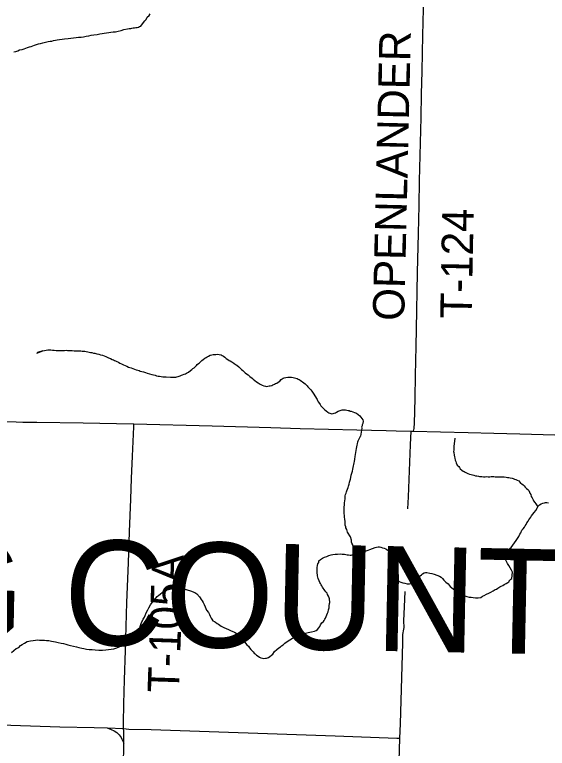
# Model space of a CAD drawing. Extents: x 2.1 to 73.9, y 4 to 26.
# Drawn here: x 42.758 to 43.238, y 21.599 to 22.261 of the extents above; entities that cross this region are included whole.
import ezdxf

# ---------------------------------------------------------------- set-up
doc = ezdxf.new("R2010")
doc.units = 0
for name, color, linetype in [('GM_X_County_Road', 7, 'Continuous'), ('GM_X_County_Text', 7, 'Continuous'), ('GM_X_Minor_River', 7, 'Continuous'), ('GM_X_Township_Road', 7, 'Continuous'), ('GM_X_Township_Road_Text', 7, 'Continuous')]:
    doc.layers.add(name, color=color, linetype=linetype)

msp = doc.modelspace()

# ---------------------------------------------------------------- linework, layer by layer
at = {"layer": 'GM_X_County_Road'}
msp.add_line((42.841, 21.61699), (42.85577, 21.61649), dxfattribs=at)
for points in [[(42.60148, 21.62491), (42.61023, 21.62468), (42.63041, 21.62408), (42.65683, 21.62308), (42.68634, 21.62181), (42.70341, 21.62107), (42.71739, 21.62063), (42.73602, 21.62004), (42.79819, 21.61818), (42.82928, 21.61742), (42.841, 21.61699)], [(42.841, 21.61699), (42.84468, 21.61557), (42.84745, 21.61451), (42.8499, 21.61286), (42.85199, 21.61075), (42.85365, 21.6083), (42.85431, 21.60697), (42.8562, 21.60316)], [(42.8562, 21.60316), (42.85611, 21.61101), (42.85596, 21.61379), (42.85577, 21.61649)], [(42.85049, 21.4548), (42.85056, 21.46392), (42.85093, 21.47093), (42.85226, 21.50191), (42.85575, 21.58424), (42.85622, 21.60133), (42.8562, 21.60316)]]:
    msp.add_lwpolyline(points, dxfattribs=at)
at = {"layer": 'GM_X_Minor_River'}
for points in [[(42.86803, 22.24923), (42.86937, 22.24959), (42.87032, 22.24996), (42.87128, 22.25032), (42.87206, 22.25126), (42.87516, 22.2552), (42.87613, 22.25632), (42.87711, 22.2584), (42.87885, 22.25989), (42.87982, 22.2614)], [(42.75662, 22.22706), (42.75853, 22.2276), (42.76025, 22.22814), (42.76197, 22.22887), (42.76426, 22.22941), (42.76598, 22.22995), (42.7677, 22.23049), (42.76923, 22.23104), (42.77076, 22.23158), (42.77229, 22.23213), (42.77401, 22.23267), (42.77554, 22.23322), (42.77726, 22.23376), (42.77898, 22.2343), (42.7807, 22.23466), (42.78299, 22.23519), (42.78776, 22.23644), (42.78948, 22.2368), (42.791, 22.23696), (42.79272, 22.23731), (42.79425, 22.23767), (42.79597, 22.23802), (42.79806, 22.23818), (42.80035, 22.23852), (42.80264, 22.23887), (42.80587, 22.2392), (42.80835, 22.23954), (42.81064, 22.23969), (42.81292, 22.24003), (42.81521, 22.24038), (42.81749, 22.24053), (42.81959, 22.24088), (42.82207, 22.24122), (42.82436, 22.24175), (42.82665, 22.2421), (42.82894, 22.24244), (42.83199, 22.24296), (42.83428, 22.2435), (42.83638, 22.24384), (42.83847, 22.244), (42.84038, 22.24435), (42.84247, 22.24451), (42.84438, 22.24486), (42.84648, 22.2452), (42.84857, 22.24536), (42.85105, 22.24589), (42.85372, 22.24642), (42.85621, 22.24733), (42.85926, 22.24785), (42.86098, 22.2482), (42.86231, 22.24837), (42.86326, 22.24855), (42.86441, 22.24872), (42.86574, 22.24889), (42.86689, 22.24906), (42.86803, 22.24923)], [(42.77766, 21.95539), (42.78282, 21.95721), (42.77804, 21.95596), (42.78282, 21.95721), (42.78454, 21.95757), (42.78606, 21.95792), (42.7874, 21.95828), (42.78892, 21.95826), (42.79025, 21.95823), (42.79177, 21.95802), (42.79329, 21.958), (42.795, 21.95778), (42.79728, 21.95755), (42.79918, 21.95752), (42.80089, 21.95769), (42.80241, 21.95766), (42.80394, 21.95783), (42.80527, 21.95781), (42.8066, 21.95779), (42.80812, 21.95776), (42.80945, 21.95774), (42.81135, 21.95733), (42.81325, 21.9573), (42.81534, 21.95727), (42.81724, 21.95724), (42.81857, 21.95703), (42.81971, 21.95701), (42.82085, 21.95699), (42.82464, 21.95617), (42.82597, 21.95596), (42.82711, 21.95575), (42.82862, 21.95535), (42.82995, 21.95514), (42.83185, 21.95473), (42.83355, 21.95432), (42.83506, 21.95372), (42.83677, 21.95332), (42.83847, 21.95272), (42.83979, 21.95213), (42.84112, 21.95154), (42.84225, 21.95114), (42.8432, 21.95075), (42.84414, 21.95035), (42.84565, 21.94957), (42.84678, 21.94917), (42.84773, 21.94858), (42.84867, 21.94819), (42.8498, 21.9476), (42.85112, 21.94701), (42.85244, 21.94623), (42.85396, 21.94564), (42.85566, 21.94485), (42.85716, 21.94406), (42.85887, 21.94347), (42.86038, 21.94268), (42.86265, 21.94189), (42.86416, 21.94129), (42.86567, 21.9407), (42.86718, 21.94011), (42.8687, 21.93989), (42.86983, 21.93949), (42.87097, 21.9391), (42.87229, 21.93869), (42.87381, 21.93829), (42.87551, 21.93769), (42.87722, 21.93729), (42.87911, 21.9365), (42.88138, 21.93608), (42.8829, 21.93568), (42.88441, 21.93527), (42.88555, 21.93487), (42.88706, 21.93447), (42.88839, 21.93445), (42.88991, 21.93423), (42.89124, 21.93402), (42.89276, 21.93381), (42.89428, 21.93379), (42.89827, 21.93353), (42.89941, 21.93351), (42.90074, 21.93349), (42.90189, 21.93367), (42.90303, 21.93365), (42.90398, 21.93382), (42.90513, 21.93418), (42.90608, 21.93436), (42.90704, 21.93472), (42.908, 21.93528), (42.90915, 21.93583), (42.91049, 21.93638), (42.91163, 21.93674), (42.91259, 21.9373), (42.91451, 21.93821), (42.91624, 21.93971), (42.9174, 21.94045), (42.91836, 21.94138), (42.91951, 21.94213), (42.92164, 21.94399), (42.92241, 21.94493), (42.92338, 21.94587), (42.92434, 21.94661), (42.9253, 21.94736)], [(42.9253, 21.94736), (42.92665, 21.94866), (42.92762, 21.94941), (42.92935, 21.95071), (42.93031, 21.95127), (42.93127, 21.95201), (42.93242, 21.95256), (42.93415, 21.95348), (42.93548, 21.95384), (42.93663, 21.95402), (42.93796, 21.95418), (42.9391, 21.95417), (42.94024, 21.95434), (42.94385, 21.95371), (42.94498, 21.95312), (42.94611, 21.95253), (42.94724, 21.95176), (42.94836, 21.95041), (42.95006, 21.94943), (42.95119, 21.94865), (42.95213, 21.94826), (42.95364, 21.94748), (42.95533, 21.94631), (42.95703, 21.94514), (42.95797, 21.94456), (42.95984, 21.94282), (42.96153, 21.94127), (42.96247, 21.9405), (42.9636, 21.93953), (42.96453, 21.93856), (42.96566, 21.93759), (42.96697, 21.93662), (42.96848, 21.93565), (42.96998, 21.9343), (42.97186, 21.93275), (42.97298, 21.93178), (42.9743, 21.93062), (42.9758, 21.92945), (42.97731, 21.92848), (42.97825, 21.92789), (42.97919, 21.92731), (42.98089, 21.92633), (42.9824, 21.92574), (42.98391, 21.92533), (42.98486, 21.92532), (42.98734, 21.92566), (42.9883, 21.92583), (42.98963, 21.92619), (42.99059, 21.92656), (42.99212, 21.92729), (42.99308, 21.92785), (42.99423, 21.92821), (42.99557, 21.92914), (42.99692, 21.93007), (42.99827, 21.93138), (43, 21.93268), (43.00096, 21.93305), (43.0023, 21.9334), (43.0042, 21.93356), (43.00515, 21.93355), (43.00629, 21.93353), (43.00743, 21.93351), (43.00895, 21.9333), (43.01028, 21.93309), (43.01141, 21.93269), (43.01255, 21.93248), (43.01349, 21.9319), (43.01444, 21.9315), (43.01538, 21.93092), (43.01651, 21.92995), (43.01745, 21.92936), (43.01857, 21.92839), (43.0197, 21.92743), (43.02064, 21.92665), (43.02158, 21.92588), (43.02232, 21.92492), (43.02307, 21.92395), (43.024, 21.92299), (43.02494, 21.92202), (43.02569, 21.92106), (43.02643, 21.91991), (43.02774, 21.91837), (43.02847, 21.91684), (43.03051, 21.91339), (43.03107, 21.91243), (43.03162, 21.91147), (43.03274, 21.90993), (43.0333, 21.90897), (43.03404, 21.90782), (43.03497, 21.90685), (43.0361, 21.9057), (43.03741, 21.90454), (43.03872, 21.90318), (43.04022, 21.90202), (43.04116, 21.90144), (43.04211, 21.90104), (43.04382, 21.90063), (43.04496, 21.90081), (43.04591, 21.90098), (43.04706, 21.90134), (43.04821, 21.90208)], [(43.04821, 21.90208), (43.04955, 21.90282), (43.05128, 21.90356), (43.05223, 21.90392), (43.05319, 21.9041), (43.05414, 21.90408), (43.05528, 21.90406), (43.05623, 21.90405), (43.05851, 21.90363), (43.05945, 21.90343), (43.0604, 21.90303), (43.06135, 21.90283), (43.06286, 21.90242), (43.06437, 21.90183), (43.06607, 21.90104), (43.06908, 21.89871), (43.0702, 21.89737), (43.07113, 21.89621), (43.07187, 21.89506), (43.07205, 21.89392), (43.07182, 21.89183), (43.07143, 21.8907), (43.07122, 21.88975), (43.07082, 21.88862), (43.07099, 21.88747), (43.06966, 21.88031)], [(43.06069, 21.78956), (43.05799, 21.79384), (43.05764, 21.79499), (43.05729, 21.79614), (43.05657, 21.79749), (43.05641, 21.79845), (43.05607, 21.79998), (43.05592, 21.80131), (43.05579, 21.80322), (43.05566, 21.80531), (43.05533, 21.80722), (43.05519, 21.80875), (43.05505, 21.81046), (43.05492, 21.81256), (43.05495, 21.81351), (43.05498, 21.81465), (43.05503, 21.81636), (43.05528, 21.81844), (43.05533, 21.82015), (43.05557, 21.82185), (43.05582, 21.82394), (43.05608, 21.8264), (43.05631, 21.82773), (43.05692, 21.82904), (43.05714, 21.82998), (43.05755, 21.83111), (43.05798, 21.83262), (43.05859, 21.83393), (43.05901, 21.83525), (43.05944, 21.83695), (43.05987, 21.83884), (43.0603, 21.84054), (43.06071, 21.84167), (43.06095, 21.84318), (43.06138, 21.84507), (43.06201, 21.84695), (43.06245, 21.84884), (43.06287, 21.85054), (43.0633, 21.85205), (43.06353, 21.85356), (43.06376, 21.85488), (43.06418, 21.8562), (43.06441, 21.85734), (43.06466, 21.85961), (43.06511, 21.86188), (43.06535, 21.86377), (43.0656, 21.86567), (43.06584, 21.86737), (43.06608, 21.86927), (43.06651, 21.87077), (43.06674, 21.87229), (43.06697, 21.87342), (43.0674, 21.87512), (43.06781, 21.87625), (43.06966, 21.88031)], [(43.15484, 21.87851), (43.1542, 21.87109), (43.15419, 21.87071), (43.15396, 21.86938), (43.15391, 21.86768), (43.15388, 21.86654), (43.15404, 21.86558), (43.15435, 21.8631), (43.15469, 21.86176), (43.15503, 21.86042), (43.15536, 21.8587), (43.15571, 21.85755), (43.15605, 21.85621), (43.15713, 21.85428), (43.15842, 21.85291), (43.15916, 21.85194), (43.15988, 21.85077), (43.16137, 21.84959), (43.16249, 21.8488), (43.16343, 21.84839), (43.16437, 21.84798), (43.16549, 21.84738), (43.1668, 21.84677), (43.16831, 21.84616), (43.16963, 21.84574), (43.17094, 21.84532), (43.17208, 21.8451), (43.17359, 21.84467), (43.17472, 21.84445), (43.17624, 21.84422), (43.17737, 21.84399), (43.17851, 21.84396), (43.17946, 21.84393), (43.18079, 21.84371), (43.18231, 21.84366), (43.18383, 21.84381), (43.18516, 21.84377), (43.18649, 21.84373), (43.18783, 21.84388), (43.18916, 21.84384), (43.1903, 21.84381), (43.19144, 21.84378), (43.19239, 21.84375), (43.19334, 21.84372), (43.19448, 21.84369), (43.19543, 21.84366), (43.19752, 21.8436), (43.19942, 21.84355), (43.20132, 21.8433), (43.20245, 21.84308), (43.20378, 21.84304), (43.20492, 21.84282), (43.20662, 21.84239), (43.20756, 21.84217), (43.20887, 21.84156), (43.21, 21.84115), (43.21113, 21.84074), (43.21263, 21.83993), (43.21374, 21.83876), (43.21428, 21.83779), (43.2154, 21.83719), (43.21671, 21.83639), (43.21763, 21.83541), (43.21837, 21.83444), (43.21966, 21.83327), (43.22097, 21.83228), (43.2217, 21.8313), (43.22223, 21.82996), (43.22258, 21.829), (43.22349, 21.82764), (43.22401, 21.82592), (43.22474, 21.82475), (43.22583, 21.82301), (43.22599, 21.82206), (43.22728, 21.8205), (43.22819, 21.81914), (43.22987, 21.81652)], [(43.21035, 21.78615), (43.21269, 21.78993), (43.2137, 21.79181), (43.2145, 21.79311), (43.21532, 21.79537), (43.2167, 21.79685), (43.21788, 21.79815), (43.21849, 21.79946), (43.21928, 21.80058), (43.22008, 21.80208), (43.22108, 21.80357), (43.22188, 21.80488), (43.22267, 21.80599), (43.22347, 21.8073), (43.22426, 21.80842), (43.22545, 21.8101), (43.22664, 21.81158), (43.22802, 21.81325), (43.22962, 21.81606), (43.23023, 21.81718), (43.2314, 21.81829), (43.23295, 21.81938), (43.2343, 21.81991), (43.23583, 21.82025), (43.23679, 21.82041), (43.23793, 21.82057), (43.23964, 21.82033)], [(43.0633, 21.77336), (43.06311, 21.77948), (43.06313, 21.78061), (43.06279, 21.78214), (43.06206, 21.78368), (43.06171, 21.78483), (43.06174, 21.78635), (43.06069, 21.78956)], [(43.19559, 21.74439), (43.19674, 21.74494), (43.19827, 21.74547), (43.19963, 21.74639), (43.20136, 21.74749), (43.20271, 21.74841), (43.20387, 21.74896), (43.20408, 21.7499), (43.20544, 21.7512), (43.2064, 21.75194), (43.20691, 21.75763), (43.206, 21.75955), (43.20491, 21.76166), (43.20362, 21.76359), (43.20252, 21.76532), (43.20179, 21.76667), (43.20107, 21.7684), (43.20053, 21.76974), (43.20036, 21.77069), (43.20038, 21.77164), (43.2006, 21.77278), (43.20119, 21.7739), (43.2016, 21.77484), (43.20219, 21.77616), (43.20298, 21.77709), (43.20376, 21.77802), (43.20454, 21.77896), (43.20589, 21.77988), (43.21035, 21.78615)], [(43.03936, 21.77184), (43.04128, 21.77275), (43.0432, 21.77327), (43.04491, 21.77343), (43.04682, 21.77395), (43.04891, 21.77391), (43.05177, 21.77403), (43.05329, 21.774), (43.05424, 21.77379), (43.05538, 21.77376), (43.05651, 21.77354), (43.05765, 21.77333), (43.05897, 21.77311), (43.0603, 21.77308), (43.06125, 21.77306), (43.06221, 21.77323), (43.06354, 21.77339), (43.06565, 21.77429), (43.06718, 21.77463), (43.06872, 21.77517), (43.07081, 21.7755), (43.07484, 21.77693), (43.07675, 21.77746), (43.07828, 21.778), (43.08308, 21.77979), (43.08423, 21.78014), (43.08575, 21.78049), (43.08689, 21.78046), (43.08803, 21.78025), (43.08973, 21.77964), (43.09124, 21.77922), (43.09256, 21.77862), (43.09368, 21.77803), (43.0948, 21.77705), (43.09514, 21.77534), (43.09625, 21.77379), (43.09698, 21.77245), (43.09732, 21.77054), (43.09784, 21.76844), (43.09837, 21.76653), (43.0989, 21.7648), (43.09943, 21.76308), (43.09977, 21.76137), (43.10011, 21.75946), (43.10045, 21.75774), (43.10079, 21.75583), (43.10131, 21.75373), (43.10185, 21.75239), (43.10258, 21.75104), (43.10351, 21.75007), (43.10483, 21.74928), (43.10633, 21.74868), (43.10803, 21.74807), (43.10973, 21.74765), (43.112, 21.74722), (43.11409, 21.74718), (43.11581, 21.74752), (43.11793, 21.7488), (43.11948, 21.7499), (43.12083, 21.75101), (43.1218, 21.75194), (43.12278, 21.75306), (43.12376, 21.75418), (43.12473, 21.7553), (43.12589, 21.75622), (43.12724, 21.75695), (43.12858, 21.7573), (43.12972, 21.75727), (43.13237, 21.75683), (43.13426, 21.75641), (43.13634, 21.75579), (43.14124, 21.75397), (43.14255, 21.753), (43.14385, 21.75183), (43.14516, 21.75047), (43.14683, 21.74872), (43.14888, 21.74696), (43.15073, 21.74464), (43.15353, 21.74268), (43.15578, 21.74092), (43.15802, 21.73935), (43.16009, 21.73835), (43.16216, 21.73717), (43.16404, 21.73636), (43.16593, 21.73575), (43.16781, 21.73514), (43.16971, 21.73491), (43.17161, 21.73468), (43.1735, 21.73444), (43.17617, 21.73457), (43.17846, 21.7349), (43.18, 21.73582), (43.18153, 21.73654), (43.18346, 21.73764), (43.18576, 21.73873), (43.1875, 21.73964), (43.18943, 21.74092), (43.19135, 21.74183), (43.19269, 21.74237), (43.19385, 21.74329), (43.19559, 21.74439)], [(42.93879, 21.71236), (42.94029, 21.71138), (42.9416, 21.71059), (42.94404, 21.70901), (42.94629, 21.70782), (42.94855, 21.70682), (42.95062, 21.70583), (42.9525, 21.70502), (42.95439, 21.70422), (42.95608, 21.70342), (42.95758, 21.70263), (42.95889, 21.70165), (42.9602, 21.70048), (42.96187, 21.69892), (42.96297, 21.697), (42.96464, 21.69525), (42.96593, 21.69351), (42.96723, 21.69197), (42.96853, 21.6908), (42.96964, 21.68944), (42.97075, 21.6879), (42.97186, 21.68673), (42.97279, 21.68557), (42.97372, 21.6846), (42.97465, 21.68382), (42.97577, 21.68285), (42.97726, 21.68167), (42.97858, 21.68088), (42.97989, 21.68028), (42.98122, 21.68006), (42.98255, 21.67984), (42.98388, 21.68), (42.98502, 21.67998), (42.98674, 21.68051), (42.99062, 21.68365), (42.99219, 21.68609), (42.99432, 21.68775), (42.99606, 21.68923), (42.99761, 21.69033), (42.99858, 21.69107), (42.99993, 21.69218), (43.00148, 21.69348), (43.00342, 21.69514), (43.00592, 21.69661), (43.00843, 21.69807), (43.01112, 21.69953), (43.01419, 21.70079), (43.01898, 21.7022), (43.02242, 21.70307), (43.02548, 21.70377), (43.02816, 21.70446), (43.02988, 21.705), (43.03103, 21.70573), (43.03221, 21.70741), (43.03319, 21.70872), (43.03379, 21.71004), (43.03479, 21.71191), (43.03634, 21.71321), (43.03712, 21.71414), (43.03752, 21.71527), (43.0383, 21.7162), (43.0389, 21.71752), (43.03951, 21.71903), (43.04011, 21.72053), (43.04071, 21.72185), (43.04094, 21.72355), (43.04136, 21.72544), (43.0416, 21.72734), (43.04183, 21.72923), (43.04204, 21.73018), (43.04206, 21.73113), (43.04191, 21.73265), (43.04193, 21.7336), (43.04157, 21.73456), (43.04103, 21.73609), (43.04011, 21.73744), (43.03957, 21.73878), (43.03845, 21.73976), (43.03772, 21.7411), (43.03551, 21.744), (43.03477, 21.74516), (43.03422, 21.74612), (43.03368, 21.74727), (43.03294, 21.74843), (43.03259, 21.74977), (43.03169, 21.75188), (43.03134, 21.75302), (43.03098, 21.75417), (43.03081, 21.75512), (43.03066, 21.75665), (43.03069, 21.75817), (43.03073, 21.75988), (43.03078, 21.76196), (43.03101, 21.76367), (43.03123, 21.76499), (43.03201, 21.76631), (43.03224, 21.76782), (43.03359, 21.76893), (43.03552, 21.77022), (43.03726, 21.77113), (43.03936, 21.77184)], [(42.7588, 21.68886), (42.76128, 21.68956), (42.76285, 21.69142), (42.76439, 21.69234), (42.7665, 21.69343), (42.76882, 21.6949), (42.77188, 21.69559), (42.77417, 21.69592), (42.77626, 21.69625), (42.77798, 21.6964), (42.77988, 21.69636), (42.7814, 21.69633), (42.78292, 21.69629), (42.78444, 21.69626), (42.78633, 21.69603), (42.78842, 21.69598), (42.79069, 21.69536), (42.79429, 21.69471), (42.79675, 21.69408), (42.7994, 21.69364), (42.80148, 21.69322), (42.80356, 21.6926), (42.80564, 21.69217), (42.80791, 21.69155), (42.81074, 21.69092), (42.8132, 21.69029), (42.81547, 21.68967), (42.81812, 21.68904), (42.82001, 21.68862), (42.82247, 21.68819), (42.82475, 21.68795), (42.8274, 21.6877), (42.83006, 21.68764), (42.83348, 21.68737), (42.8369, 21.68729), (42.83994, 21.68741), (42.84719, 21.68839), (42.84872, 21.68893), (42.85122, 21.69001), (42.85313, 21.69073), (42.85525, 21.69163), (42.85736, 21.69253), (42.85946, 21.69325), (42.8612, 21.69416), (42.86294, 21.69545), (42.86448, 21.69655), (42.86566, 21.69823), (42.86704, 21.70029), (42.86842, 21.70254), (42.86924, 21.70518), (42.87043, 21.70744), (42.87105, 21.70951), (42.87185, 21.71139), (42.87245, 21.71271), (42.87304, 21.71384), (42.87365, 21.71534), (42.87464, 21.71703), (42.87524, 21.71854), (42.87624, 21.72079), (42.87764, 21.72361), (42.87863, 21.7253), (42.88021, 21.72811), (42.88178, 21.73017), (42.88335, 21.73241), (42.8851, 21.73408), (42.88627, 21.73557), (42.88763, 21.73687), (42.88879, 21.7378), (42.89092, 21.73946), (42.89207, 21.74), (42.89361, 21.74092), (42.89496, 21.74165), (42.89649, 21.74199), (42.89764, 21.74235), (42.89917, 21.7427), (42.90088, 21.74285), (42.90279, 21.74318), (42.90432, 21.74334), (42.90603, 21.74349), (42.90793, 21.74326), (42.91019, 21.74245), (42.91322, 21.74181), (42.91623, 21.74079), (42.92019, 21.73918), (42.92188, 21.738), (42.92429, 21.73529), (42.92502, 21.73433), (42.92576, 21.73298), (42.92668, 21.73182), (42.9276, 21.73028), (42.92851, 21.72855), (42.9296, 21.72643), (42.93067, 21.72337), (42.93253, 21.72124), (42.93343, 21.71932), (42.93416, 21.71778), (42.93489, 21.71625), (42.93562, 21.71528), (42.93654, 21.71374), (42.93785, 21.71295), (42.93879, 21.71236)], [(42.75453, 21.68515), (42.7588, 21.68886)]]:
    msp.add_lwpolyline(points, dxfattribs=at)
at = {"layer": 'GM_X_Township_Road'}
msp.add_line((43.11547, 21.88482), (43.11777, 21.88478), dxfattribs=at)
for points in [[(43.11777, 21.88478), (43.11809, 21.8873), (43.1182, 21.88823), (43.11844, 21.89133), (43.11906, 21.91463), (43.11947, 21.93513), (43.12004, 21.96154), (43.12025, 21.97677), (43.12126, 22.02805), (43.1221, 22.06316), (43.12265, 22.08864), (43.12315, 22.1107), (43.12362, 22.1337), (43.1245, 22.16787), (43.12484, 22.18901), (43.12534, 22.20983), (43.12616, 22.24214), (43.12642, 22.25364), (43.12693, 22.27912)], [(42.6144, 21.89578), (42.62669, 21.89559), (42.75881, 21.89321), (42.765, 21.89313), (42.77741, 21.89304), (42.81938, 21.89236), (42.86445, 21.89154), (42.86508, 21.89152)], [(42.85577, 21.61649), (42.8557, 21.62126), (42.85593, 21.63866), (42.85656, 21.66041), (42.85747, 21.68681), (42.85873, 21.73032), (42.86025, 21.76605), (42.86133, 21.79401), (42.86241, 21.82353), (42.86311, 21.84217), (42.8639, 21.86235), (42.86496, 21.88875), (42.86508, 21.89152)], [(42.86508, 21.89152), (42.93594, 21.88968), (42.98876, 21.88811), (43.01515, 21.88731), (43.06644, 21.88619), (43.09283, 21.88547), (43.1021, 21.88517), (43.11547, 21.88482)], [(43.11261, 21.81474), (43.11318, 21.82566), (43.11503, 21.8725), (43.11547, 21.88482)], [(43.11777, 21.88478), (43.14204, 21.88438), (43.16693, 21.88368), (43.19026, 21.883), (43.21359, 21.88234), (43.3085, 21.87971), (43.32872, 21.87925), (43.33961, 21.87905), (43.36914, 21.87846), (43.40492, 21.87753), (43.43137, 21.87675), (43.45313, 21.8764), (43.47179, 21.87595), (43.56359, 21.87357), (43.61932, 21.87224)], [(43.1054, 21.60779), (43.10583, 21.62063), (43.10815, 21.69373), (43.10806, 21.69839), (43.10801, 21.7015), (43.10904, 21.70604), (43.1092, 21.70758), (43.10894, 21.7138), (43.10944, 21.72623), (43.11007, 21.7402)], [(42.85577, 21.61649), (42.8606, 21.61608), (42.88064, 21.61548), (43.04678, 21.60987), (43.10268, 21.60789), (43.1054, 21.60779)], [(43.09746, 21.37994), (43.09844, 21.40137), (43.10107, 21.48224), (43.10212, 21.51489), (43.10399, 21.56621), (43.1054, 21.60779)]]:
    msp.add_lwpolyline(points, dxfattribs=at)

# ---------------------------------------------------------------- texts
at = {"layer": 'GM_X_County_Text'}
msp.add_text('PAULDING COUNTY', height=0.094697, rotation=358.83177, dxfattribs=at).set_placement((42.1185, 21.70637))
at = {"layer": 'GM_X_Township_Road_Text'}
for s, rotation, p in [('OPENLANDER', 88.66297, (43.1092, 21.98417)), ('T-124', 88.87621, (43.1701, 21.98627)), ('T-105A', 88.06099, (42.90583, 21.64847))]:
    msp.add_text(s, height=0.028409, rotation=rotation, dxfattribs=at).set_placement(p)

doc.saveas('drawing.dxf')
